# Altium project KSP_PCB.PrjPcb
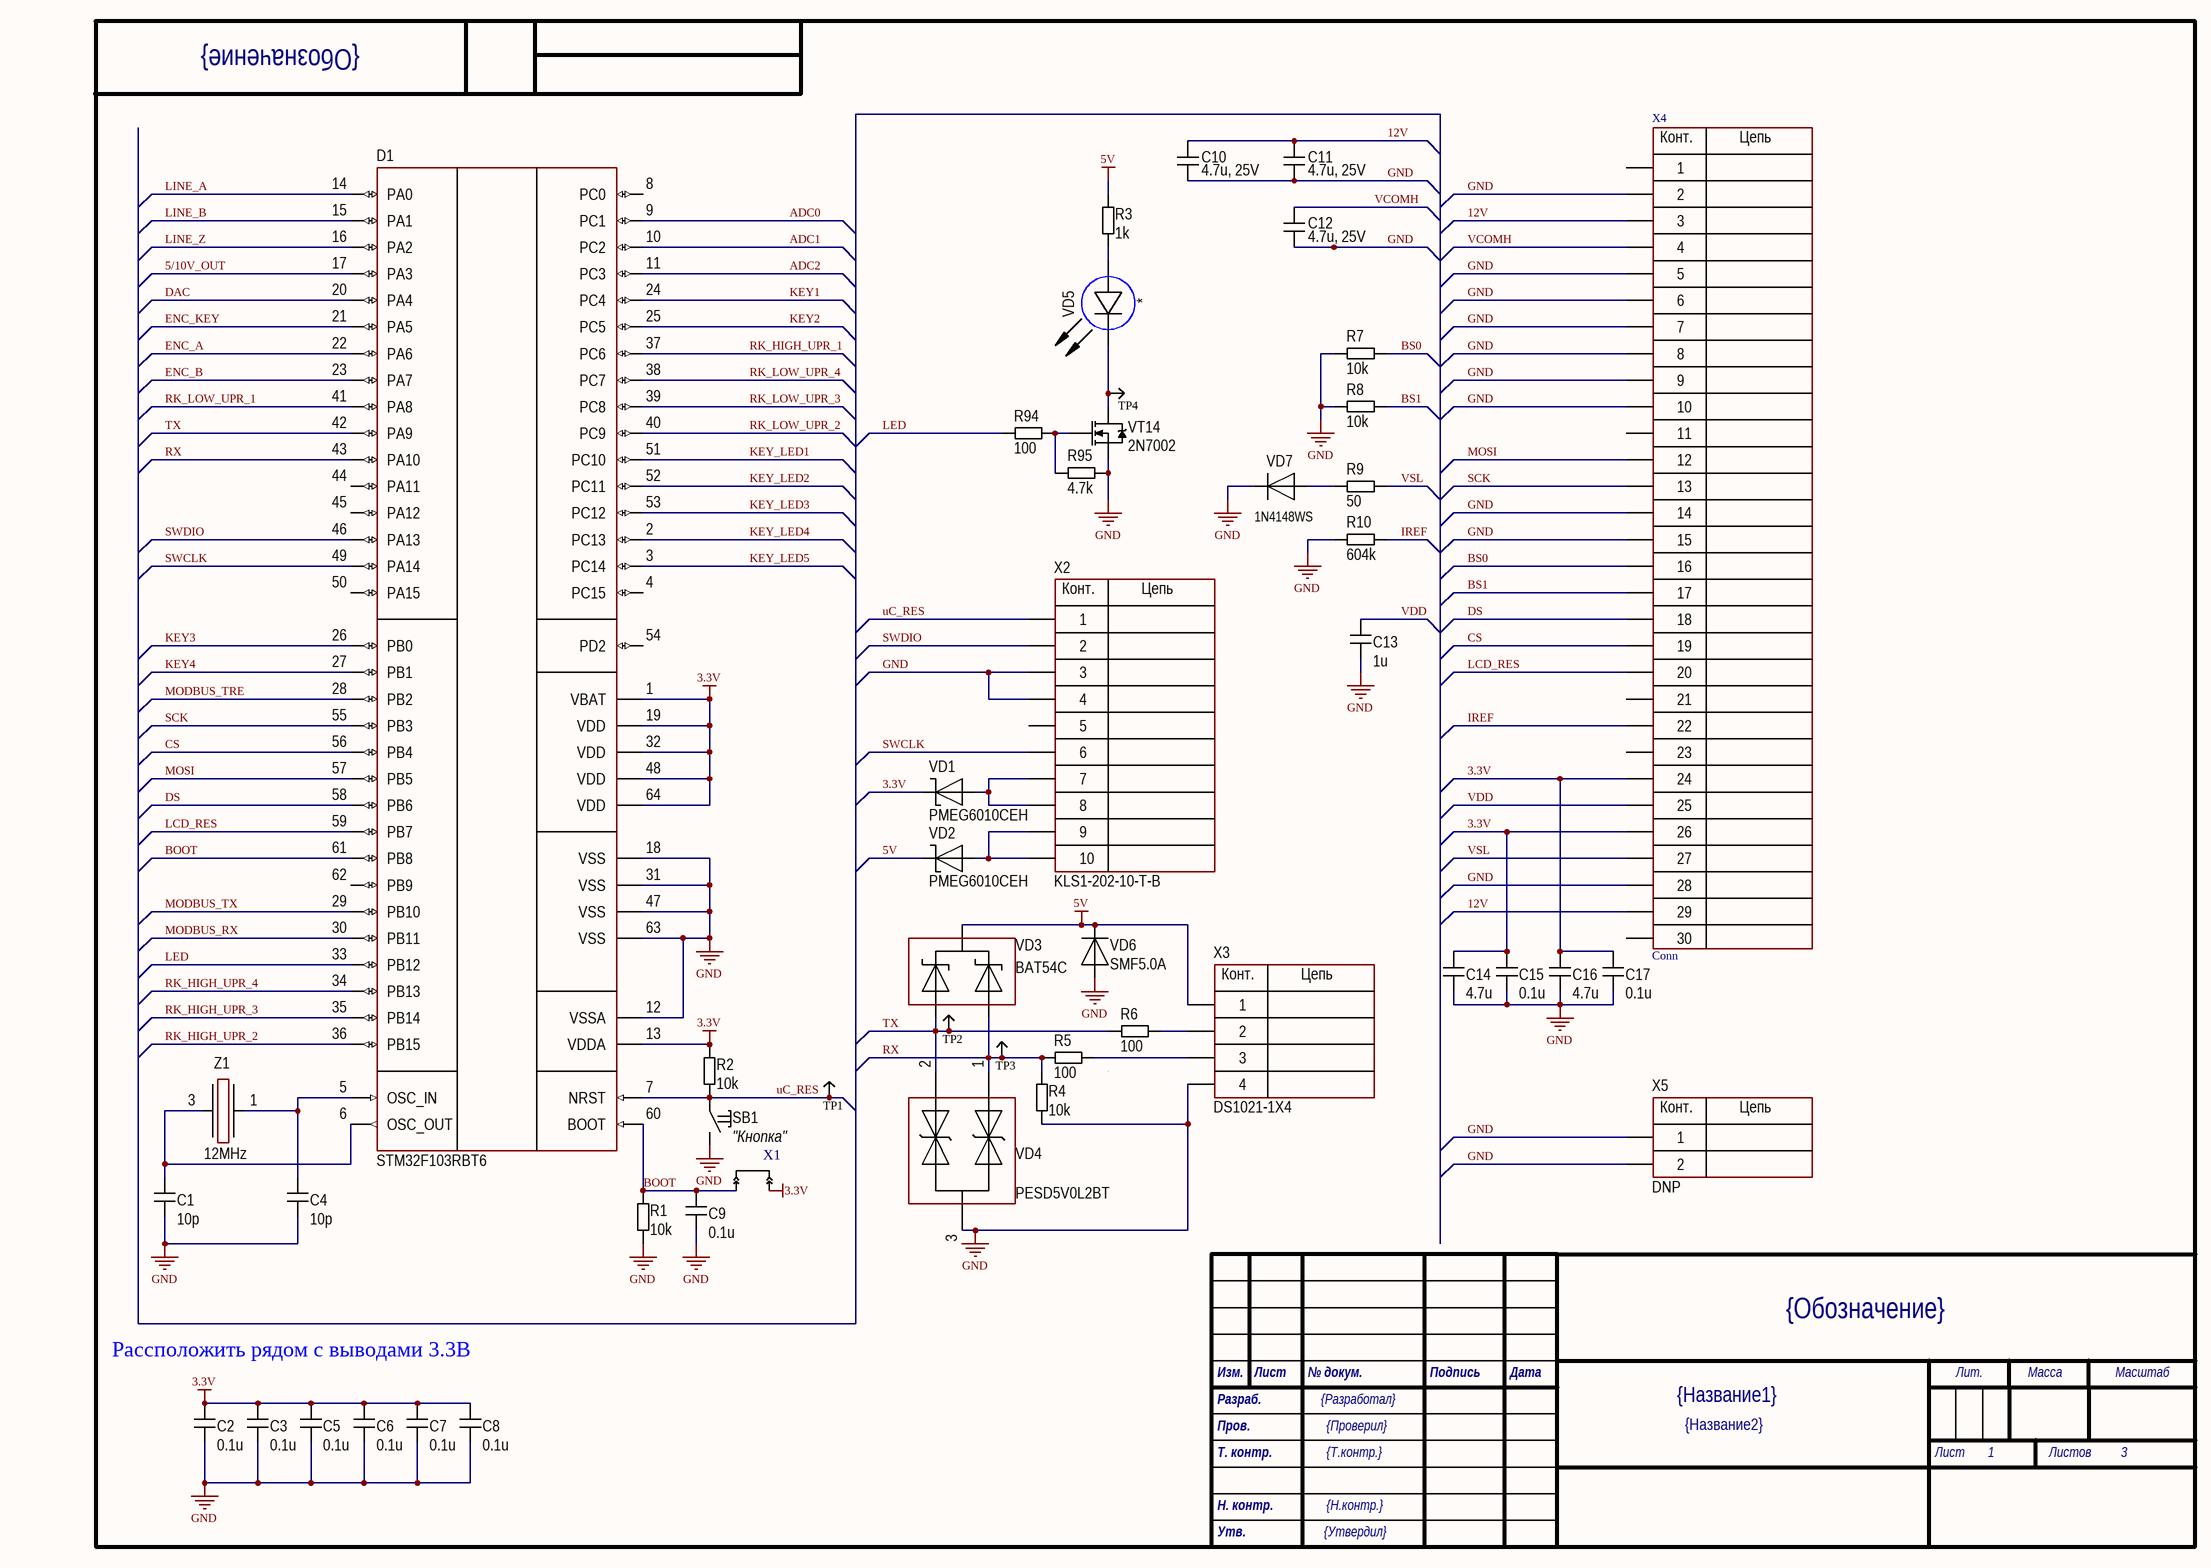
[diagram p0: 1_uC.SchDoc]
3 sheets, 210 parts. Net scope: global (net labels, ports and power ports of the same name join across sheets).
Board file: KSP_PCB.PcbDoc
Sheets:
  1_uC.SchDoc
  2_Connection.SchDoc
  3_RK.SchDoc

## Sheet 1_uC.SchDoc
size 414 x 293 mm; SheetNumber: 1; SheetTotal: 3; PageSetup: Record=PageOptionsZCenterHorizontal=TrueZCenterVertical=TrueZPrintScale=1.00ZXCorrection=0.00ZYCorrection=0.00ZPrintKind=1ZBorderSize=5000000ZLeftOffset=0ZBottomOffset=0ZOrientation=2ZPaperLength=1000ZPaperWidth=1000ZScale=100ZPaperSource=7ZPrintQuality=-4ZMediaType=1ZDitherType=10ZPaperKind=A3ZPrintScaleMode=0; Razrabotal: {Разработал}; Proveril: {Проверил}; Tkontr: {Т.контр.}; Nkontr: {Н.контр.}; Ytverdil: {Утвердил}; Nazvanie1: {Название1}; Nazvanie2: {Название2}; Oboznachenie: {Обозначение}

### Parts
C1  10p  [CH0402C]
C2  0.1u  [CH0603C]
C3  0.1u  [CH0603C]
C4  10p  [CH0402C]
C5  0.1u  [CH0603C]
C6  0.1u  [CH0603C]
C7  0.1u  [CH0603C]
C8  0.1u  [CH0603C]
C9  0.1u  [CH0603C]
C10  4.7u, 25V  [CH0805C]
C11  4.7u, 25V  [CH0805C]
C12  4.7u, 25V  [CH0805C]
C13  1u  [CH0603C]
C14  4.7u  [CH0603C]
C15  0.1u  [CH0603C]
C16  4.7u  [CH0603C]
C17  0.1u  [CH0603C]
D1  STM32F103RBT6  [64-LQFP]
R1  10k  [CH0603R]
R2  10k  [CH0603R]
R3  1k  [CH0805R]
R4  10k  [CH0603R]
R5  100  [CH0603R]
R6  100  [CH0603R]
R7  10k  [CH0603R]
R8  10k  [CH0603R]
R9  50  [CH0603R]
R10  604k  [CH0603R]
R94  100  [CH0603R]
R95  4.7k  [CH0603R]
SB1  "Кнопка"  [TL1014BF160QG]
TP1  (no value)  [TestPoint]
TP2  (no value)  [TestPoint]
TP3  (no value)  [TestPoint]
TP4  (no value)  [TestPoint]
VD1  PMEG6010CEH  [SOD123F]
VD2  PMEG6010CEH  [SOD123F]
VD3  BAT54C  [SOT23_123]
VD4  PESD5V0L2BT  [SOT23_132]
VD5  *  [CH0603LB]
VD6  SMF5.0A  [SOD123F]
VD7  1N4148WS  [SOD323]
VT14  2N7002  [SOT23_123]
X1  JMP-2  [PLS-2]  (value not drawn)
X2  KLS1-202-10-T-B  [CON: IDC-10MS]
X3  DS1021-1X4  [CON: PLS-4]
X4  Conn  [FPC-30]
X5  DNP  [CON: PLS-2]
Z1  12MHz  [OSC: 2520]

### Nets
3.3V: C2.2 C3.2 C5.2 C6.2 C7.2 C8.2 C14.2 C15.2 C16.2 C17.2 D1.1(VBAT) D1.13(VDDA) D1.19(VDD) D1.32(VDD) D1.48(VDD) D1.64(VDD) R2.2 VD1.2 X1.2 X4.24 X4.26
5V: R3.2 VD2.2 VD3.2 VD6.2 X3.1
12V: C10.2 C11.2 X4.3 X4.29
GND: C1.1 C2.1 C3.1 C4.1 C5.1 C6.1 C7.1 C8.1 C9.1 C10.1 C11.1 C12.1 C13.1 C14.1 C15.1 C16.1 C17.1 D1.12(VSSA) D1.18(VSS) D1.31(VSS) D1.47(VSS) D1.63(VSS) R1.1 R4.2 R7.1 R8.1 R10.1 R95.1 SB1.2 VD4.3 VD6.1 VD7.2 VT14.3(S) X2.3 X2.4 X3.4 X4.2 X4.5 X4.6 X4.7 X4.8 X4.9 X4.10 X4.14 X4.15 X4.28 X5.1 X5.2
5/10V_OUT: D1.17(PA3)
ADC0: D1.9(PC1)
ADC1: D1.10(PC2)
ADC2: D1.11(PC3)
BOOT: C9.2 D1.60(BOOT) D1.61(PB8) R1.2 X1.1
BS0: R7.2 X4.16
BS1: R8.2 X4.17
CS: D1.56(PB4) X4.19
DAC: D1.20(PA4)
DS: D1.58(PB6) X4.18
ENC_A: D1.22(PA6)
ENC_B: D1.23(PA7)
ENC_KEY: D1.21(PA5)
IREF: R10.2 X4.22
KEY1: D1.24(PC4)
KEY2: D1.25(PC5)
KEY3: D1.26(PB0)
KEY4: D1.27(PB1)
KEY_LED1: D1.51(PC10)
KEY_LED2: D1.52(PC11)
KEY_LED3: D1.53(PC12)
KEY_LED4: D1.2(PC13)
KEY_LED5: D1.3(PC14)
LCD_RES: D1.59(PB7) X4.20
LED: D1.33(PB12) R94.2
LINE_A: D1.14(PA0)
LINE_B: D1.15(PA1)
LINE_Z: D1.16(PA2)
MODBUS_RX: D1.30(PB11)
MODBUS_TRE: D1.28(PB2)
MODBUS_TX: D1.29(PB10)
MOSI: D1.57(PB5) X4.12
RK_HIGH_UPR_1: D1.37(PC6)
RK_HIGH_UPR_2: D1.36(PB15)
RK_HIGH_UPR_3: D1.35(PB14)
RK_HIGH_UPR_4: D1.34(PB13)
RK_LOW_UPR_1: D1.41(PA8)
RK_LOW_UPR_2: D1.40(PC9)
RK_LOW_UPR_3: D1.39(PC8)
RK_LOW_UPR_4: D1.38(PC7)
RX: D1.43(PA10) R4.1 R5.2 TP3.0 VD3.1 VD4.1
SCK: D1.55(PB3) X4.13
SWCLK: D1.49(PA14) X2.6
SWDIO: D1.46(PA13) X2.2
TX: D1.42(PA9) R6.2 TP2.0 VD3.3 VD4.2
uC_RES: D1.7(NRST) R2.1 SB1.1 TP1.0 X2.1
VCOMH: C12.2 X4.4
VDD: C13.2 X4.25
VSL: R9.2 X4.27
NetC1_2: C1.2 D1.6(OSC_OUT) Z1.3
NetC4_2: C4.2 D1.5(OSC_IN) Z1.1
NetR3_1: R3.1 VD5.1(A)
NetR5_1: R5.1 X3.3
NetR6_1: R6.1 X3.2
NetR9_1: R9.1 VD7.1
NetR94_1: R94.1 R95.2 VT14.1(G)
NetTP4_0: TP4.0 VD5.2(C) VT14.2(D)
NetVD1_1: VD1.1 X2.7 X2.8
NetVD2_1: VD2.1 X2.9 X2.10

Not connected (* = marked no-connect by the designer): D1 4(PC15) 8(PC0) 44(PA11) 45(PA12) 50(PA15) 54(PD2) 62(PB9); X2 5; X4 1 11 21 23 30

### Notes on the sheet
- Рассположить рядом с выводами 3.3В

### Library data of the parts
C1 C4 = Capacitor: Model: AC0402JRNPO9BN100
C2 C3 C5-C9 C15 C17 = Capacitor: Model: 06035C104JAT2A
C10-C12 = Capacitor: Model: 08053C475KAT2A
C13 = Capacitor: Model: 0603B105K250NT
C14 C16 = Capacitor: Model: 06036D475KAT2A
D1 = STM32F103RBT6: Cortex-M3; Manufacturer: STMicroelectronics
R1 R2 R4 R7 R8 = Resistor: Model: CR0603-FX-1002ELF
R3 = Resistor: Model: CR0805-FX-1001ELF
R5 R6 R94 = Resistor: Model: CR0603-JW-101ELF
R9 = Resistor: Model: CR0603-FX-49R9ELF
R10 = Resistor: Model: CR0603-FX-6043ELF
R95 = Resistor: Model: CR0603-FX-4701ELF
SB1 = Tactile switches: 6x6 mm
TP1-TP4 = TestPoint
VD1 VD2 = Diod Schottky
VD3 = Diod Schottky Array v.1
VD4 = TVS Array
VD5 = LED_1: Model: KPT-1608SGC
VD6 = Diod: Part Num: SMAF5.0A
VD7 = Diod
VT14 = N-chanel: Mosfet
X1 = JMP-2: Model: DNP
X2 = 10-Connector
X3 = 4-Connector
X4 = 30-Connector: Model: KLS1-242G-2.0-30-T-R
X5 = 2-Connector
Z1 = Oscillator: Model: ECS-120-10-36B2-JTN-TR

## Sheet 2_Connection.SchDoc
size 414 x 293 mm; SheetNumber: 2; SheetTotal: 3; PageSetup: Record=PageOptionsZCenterHorizontal=TrueZCenterVertical=TrueZPrintScale=1.00ZXCorrection=0.00ZYCorrection=0.00ZPrintKind=1ZBorderSize=5000000ZLeftOffset=0ZBottomOffset=0ZOrientation=2ZPaperLength=1000ZPaperWidth=1000ZScale=100ZPaperSource=7ZPrintQuality=-4ZMediaType=1ZDitherType=10ZPaperKind=A3ZPrintScaleMode=0; Razrabotal: {Разработал}; Proveril: {Проверил}; Tkontr: {Т.контр.}; Nkontr: {Н.контр.}; Ytverdil: {Утвердил}; Nazvanie1: {Название1}; Nazvanie2: {Название2}; Oboznachenie: {Обозначение}
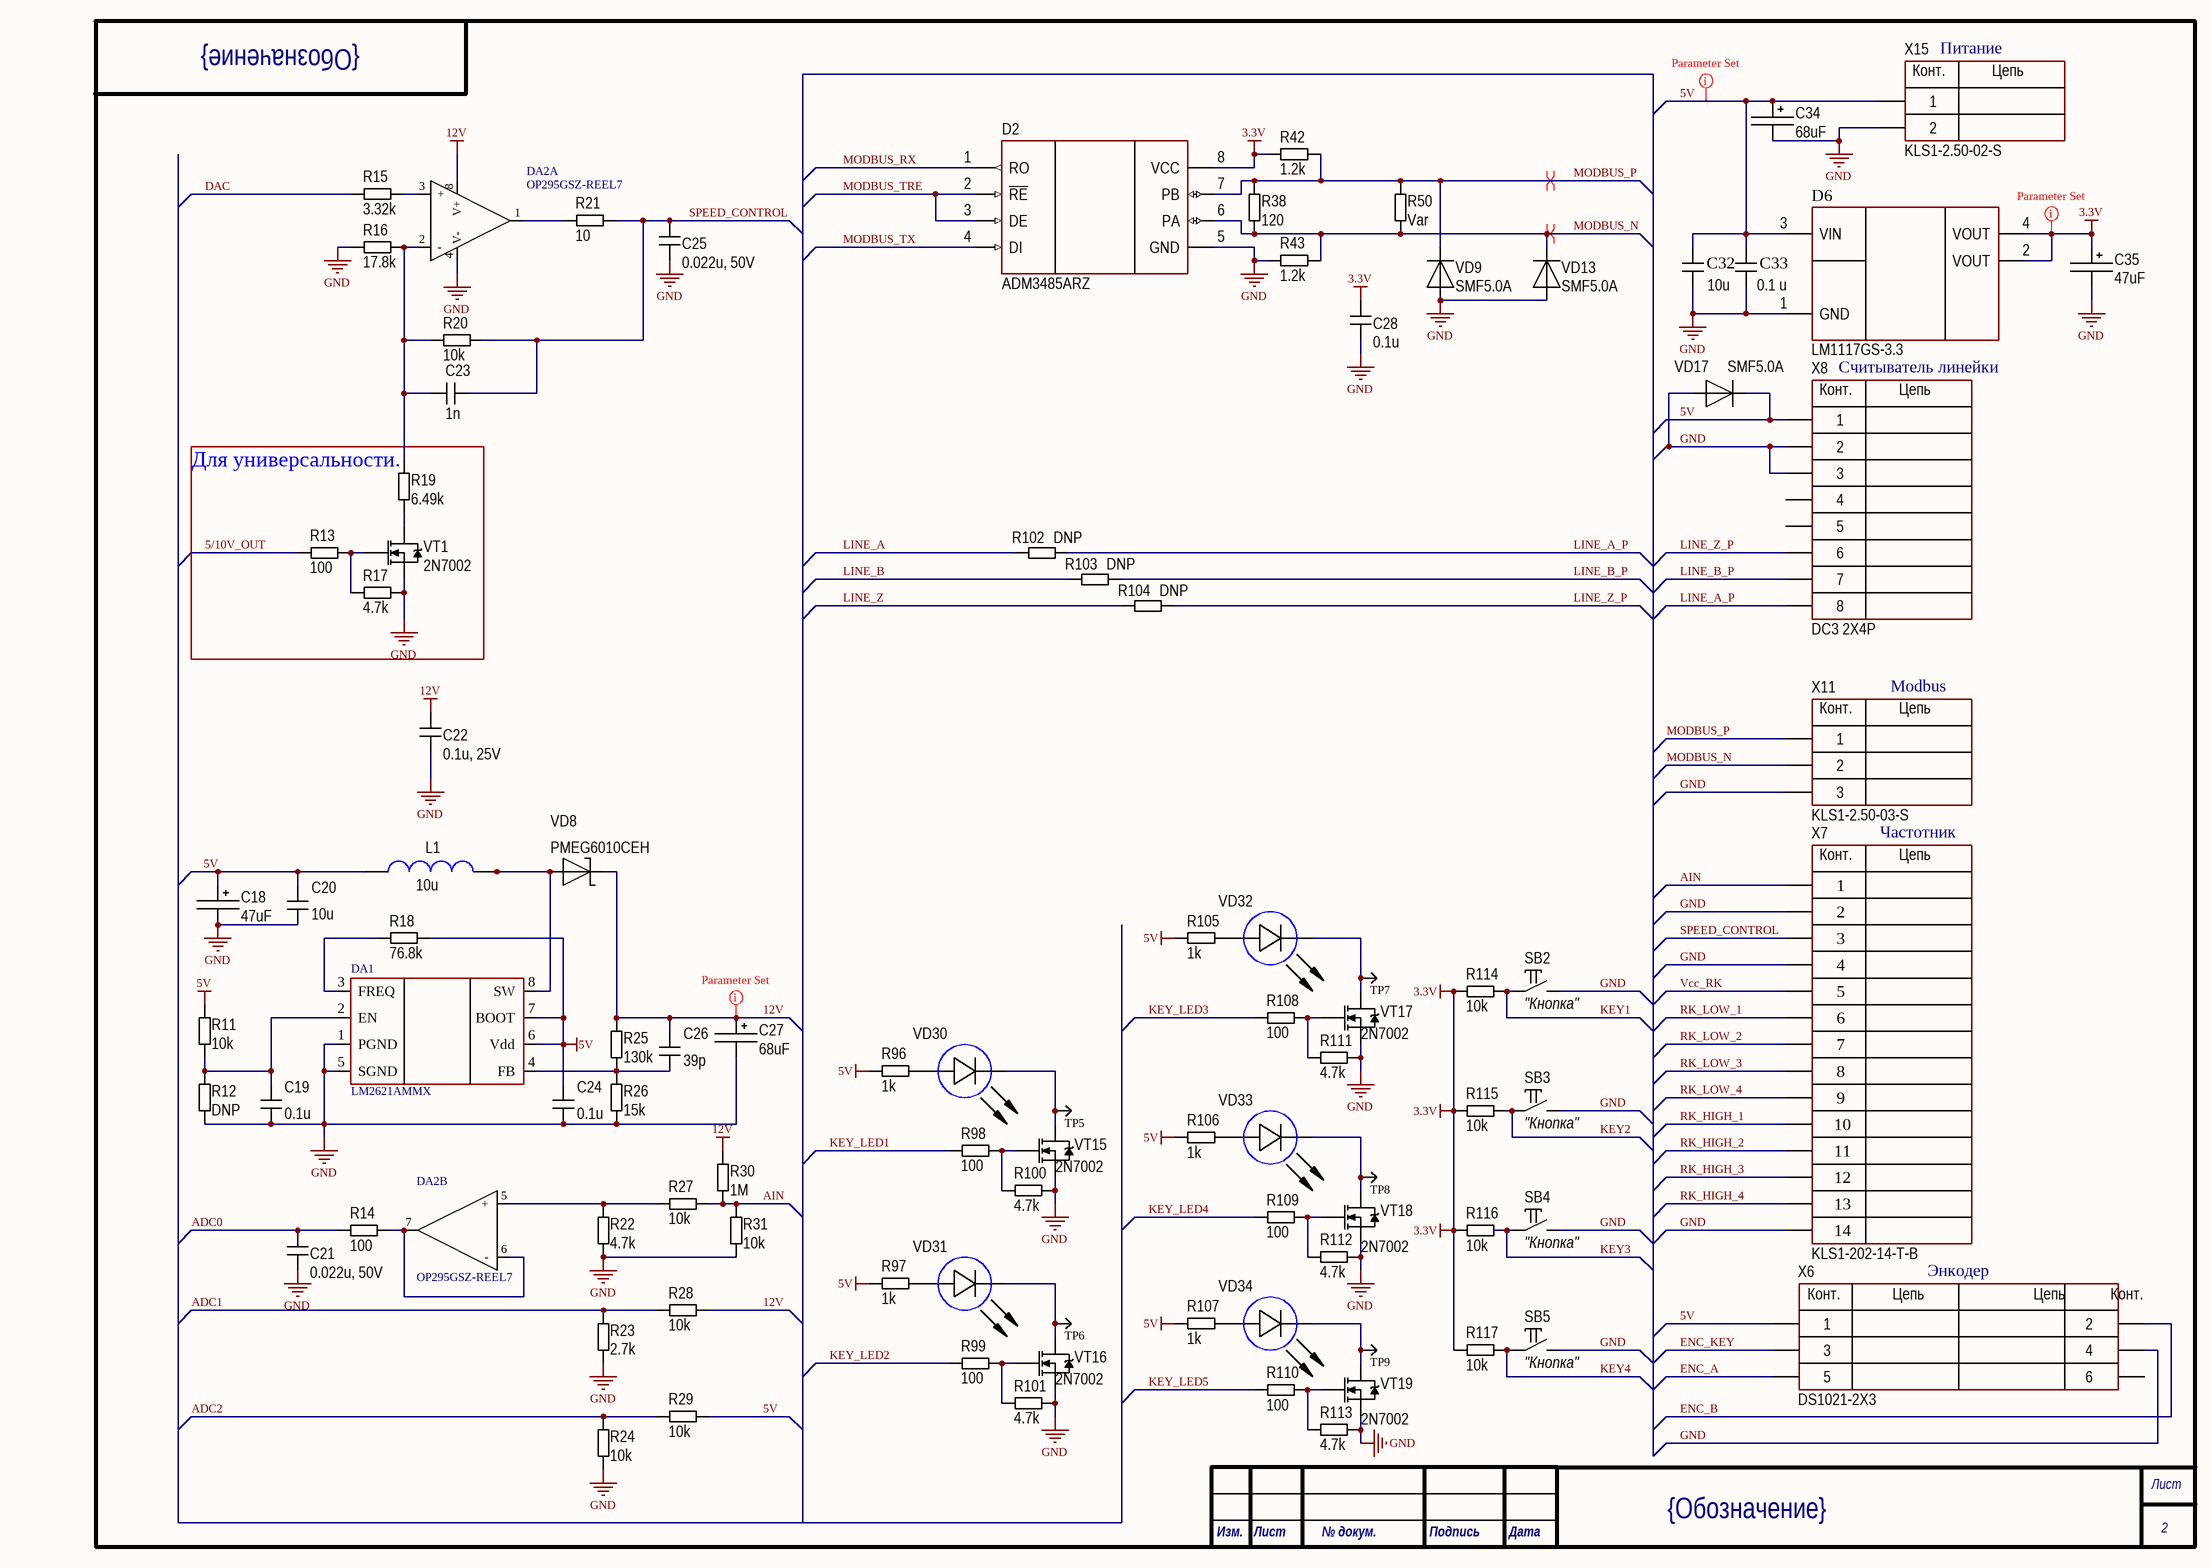
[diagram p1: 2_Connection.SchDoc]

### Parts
C18  47uF  [TANTAL_B]
C19  0.1u  [CH0603C]
C20  10u  [CH0603C]
C21  0.022u, 50V  [CH0603C]
C22  0.1u, 25V  [CH0603C]
C23  1n  [CH0603C]
C24  0.1u  [CH0603C]
C25  0.022u, 50V  [CH0603C]
C26  39p  [CH0603C]
C27  68uF  [TANTAL_D]
C28  0.1u  [CH0603C]
C32  10u  [CH0805C]
C33  0.1 u  [CH0603C]
C34  68uF  [TANTAL_B]
C35  47uF  [TANTAL_A]
D2  ADM3485ARZ  [8-SOIC]
D6  LM1117GS-3.3  [SOT223]
DA1  LM2621AMMX  [8-SSOP]
DA2  OP295GSZ-REEL7  [8-SOIC]  (parts A,B of 2)
L1  10u  [IND: IHLP2020]
R11  10k  [CH0603R]
R12  DNP  [CH0603R]
R13  100  [CH0603R]
R14  100  [CH0603R]
R15  3.32k  [CH0603R]
R16  17.8k  [CH0603R]
R17  4.7k  [CH0603R]
R18  76.8k  [CH0603R]
R19  6.49k  [CH0603R]
R20  10k  [CH0603R]
R21  10  [CH0603R]
R22  4.7k  [CH0603R]
R23  2.7k  [CH0603R]
R24  10k  [CH0603R]
R25  130k  [CH0603R]
R26  15k  [CH0603R]
R27  10k  [CH0603R]
R28  10k  [CH0603R]
R29  10k  [CH0603R]
R30  1M  [CH0603R]
R31  10k  [CH0603R]
R38  120  [CH1206R]
R42  1.2k  [CH0603R]
R43  1.2k  [CH0603R]
R50  Var  [CH1206R]
R96  1k  [CH0805R]
R97  1k  [CH0805R]
R98  100  [CH0603R]
R99  100  [CH0603R]
R100  4.7k  [CH0603R]
R101  4.7k  [CH0603R]
R102  DNP  [CH0603R]
R103  DNP  [CH0603R]
R104  DNP  [CH0603R]
R105  1k  [CH0805R]
R106  1k  [CH0805R]
R107  1k  [CH0805R]
R108  100  [CH0603R]
R109  100  [CH0603R]
R110  100  [CH0603R]
R111  4.7k  [CH0603R]
R112  4.7k  [CH0603R]
R113  4.7k  [CH0603R]
R114  10k  [CH0603R]
R115  10k  [CH0603R]
R116  10k  [CH0603R]
R117  10k  [CH0603R]
SB2  "Кнопка"  [BUT: SKQGADE010]
SB3  "Кнопка"  [BUT: SKQGADE010]
SB4  "Кнопка"  [BUT: SKQGADE010]
SB5  "Кнопка"  [BUT: SKQGADE010]
TP5  (no value)  [TestPoint]
TP6  (no value)  [TestPoint]
TP7  (no value)  [TestPoint]
TP8  (no value)  [TestPoint]
TP9  (no value)  [TestPoint]
VD8  PMEG6010CEH  [SOD123F]
VD9  SMF5.0A  [SOD123F]
VD13  SMF5.0A  [SOD123F]
VD17  SMF5.0A  [SOD123F]
VD30  BLUE  [CH0603LB]  (value not drawn)
VD31  BLUE  [CH0603LB]  (value not drawn)
VD32  BLUE  [CH0603LB]  (value not drawn)
VD33  BLUE  [CH0603LB]  (value not drawn)
VD34  BLUE  [CH0603LB]  (value not drawn)
VT1  2N7002  [SOT23_123]
VT15  2N7002  [SOT23_123]
VT16  2N7002  [SOT23_123]
VT17  2N7002  [SOT23_123]
VT18  2N7002  [SOT23_123]
VT19  2N7002  [SOT23_123]
X6  DS1021-2X3  [CON: PLD-6 (without body)]
X7  KLS1-202-14-T-B  [CON: IDC-14MS]
X8  DC3 2X4P  [CON: DC3 2x4P]
X11  KLS1-2.50-03-S  [CON: CWF-3]
X15  KLS1-2.50-02-S  [CON: CWF-2]

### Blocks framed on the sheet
Для универсальности.: R13 R17 R19 VT1

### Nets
3.3V: C28.2 C35.1 D2.8(VCC) D6.2(VOUT) D6.4(VOUT) R42.2 R114.2 R115.2 R116.2 R117.2
5V: C18.1 C20.2 C24.2 C32.2 C33.2 C34.1 D6.3(VIN) DA1.6(Vdd) DA1.7(BOOT) L1.2 R11.1 R18.1 R29.1 R96.2 R97.2 R105.2 R106.2 R107.2 VD17.2 X6.1 X8.1 X15.1
12V: C22.2 C26.2 C27.1 DA2.8(V+) R25.1 R28.1 R30.1 VD8.2
GND: C18.2 C19.1 C20.1 C21.1 C22.1 C24.1 C25.1 C27.2 C28.1 C32.1 C33.1 C34.2 C35.2 D2.5(GND) D6.1(GND) DA1.1(PGND) DA1.5(SGND) DA2.4(V-) R12.2 R16.2 R17.1 R22.2 R23.2 R24.2 R26.2 R31.2 R43.2 R100.1 R101.1 R111.1 R112.1 R113.1 SB2.2 SB3.2 SB4.2 SB5.2 VD9.1 VD13.1 VD17.1 VT1.3(S) VT15.3(S) VT16.3(S) VT17.3(S) VT18.3(S) VT19.3(S) X6.4 X7.2 X7.4 X7.14 X8.2 X8.3 X11.3 X15.2
5/10V_OUT: R13.2
ADC0: C21.2 R14.1
ADC1: R23.1 R28.2
ADC2: R24.1 R29.2
AIN: R27.1 R30.2 R31.1 X7.1
DAC: R15.2
ENC_A: X6.5
ENC_B: X6.2
ENC_KEY: X6.3
KEY1: R114.1 SB2.1
KEY2: R115.1 SB3.1
KEY3: R116.1 SB4.1
KEY4: R117.1 SB5.1
KEY_LED1: R98.2
KEY_LED2: R99.2
KEY_LED3: R108.2
KEY_LED4: R109.2
KEY_LED5: R110.2
LINE_A: R102.2
LINE_A_P: R102.1 X8.8
LINE_B: R103.2
LINE_B_P: R103.1 X8.7
LINE_Z: R104.2
LINE_Z_P: R104.1 X8.6
MODBUS_N: D2.6(PA) R38.1 R43.1 R50.1 VD13.2 X11.2
MODBUS_P: D2.7(PB) R38.2 R42.1 R50.2 VD9.2 X11.1
MODBUS_RX: D2.1(RO)
MODBUS_TRE: D2.2(~{RE}) D2.3(DE)
MODBUS_TX: D2.4(DI)
RK_HIGH_1: X7.10
RK_HIGH_2: X7.11
RK_HIGH_3: X7.12
RK_HIGH_4: X7.13
RK_LOW_1: X7.6
RK_LOW_2: X7.7
RK_LOW_3: X7.8
RK_LOW_4: X7.9
SPEED_CONTROL: C23.1 C25.2 R20.1 R21.1 X7.3
Vcc_RK: X7.5
NetC19_2: C19.2 DA1.2(EN) R11.2 R12.1
NetC23_2: C23.2 DA2.2(-) R16.1 R19.1 R20.2
NetC26_1: C26.1 DA1.4(FB) R25.2 R26.1
NetDA1_3: DA1.3(FREQ) R18.2
NetDA1_8: DA1.8(SW) L1.1 VD8.1
NetDA2_1: DA2.1(OUT) R21.2
NetDA2_3: DA2.3(+) R15.1
NetDA2_5: DA2.5(+) R22.1 R27.2
NetDA2_6: DA2.6(-) DA2.7(OUT) R14.2
NetR13_1: R13.1 R17.2 VT1.1(G)
NetR19_2: R19.2 VT1.2(D)
NetR96_1: R96.1 VD30.1(A)
NetR97_1: R97.1 VD31.1(A)
NetR98_1: R98.1 R100.2 VT15.1(G)
NetR99_1: R99.1 R101.2 VT16.1(G)
NetR105_1: R105.1 VD32.1(A)
NetR106_1: R106.1 VD33.1(A)
NetR107_1: R107.1 VD34.1(A)
NetR108_1: R108.1 R111.2 VT17.1(G)
NetR109_1: R109.1 R112.2 VT18.1(G)
NetR110_1: R110.1 R113.2 VT19.1(G)
NetTP5_0: TP5.0 VD30.2(C) VT15.2(D)
NetTP6_0: TP6.0 VD31.2(C) VT16.2(D)
NetTP7_0: TP7.0 VD32.2(C) VT17.2(D)
NetTP8_0: TP8.0 VD33.2(C) VT18.2(D)
NetTP9_0: TP9.0 VD34.2(C) VT19.2(D)

Not connected (* = marked no-connect by the designer): X6 6; X8 4 5

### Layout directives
differential pair: MODBUS_N, MODBUS_P
rule Supply Nets [Voltage = 5.000]: 5V
rule Supply Nets [Voltage = 12.00]: 12V
rule Supply Nets [Voltage = 3.300]: 3.3V

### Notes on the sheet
- Питание
- Считыватель линейки
- Modbus
- Частотник
- (near X6) Энкодер

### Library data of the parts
C18 = TantalCap: Model: 293D476X9010B2TE3
C19 C22 C24 C28 C33 = Capacitor: Model: 06035C104JAT2A
C20 C32 = Capacitor: Model: GRM21BR71A106KE51
C21 C25 = Capacitor: Model: 06035C223JAT2A
C23 = Capacitor: Model: 06035A102JAT2A
C26 = Capacitor: Model: CC0603JRNPO9BN390
C27 = TantalCap: Model: 293D686X9020D2TE3
C34 = TantalCap: Model: 293D686X9010B2TE3
C35 = TantalCap: Model: 293D476X96R3A2TE3
D2 = ADM3485ARZ: RS485; Manufacturer: Analog Devices Inc.; Model: ADM3485ARZ-REEL7
D6 = LDL1117S33R: LDO; Manufacturer: STMicroelectronics
DA1 = LM2623AMMX
DA2 = OP295
L1 = Inductor: Model: IHLP2020CZER100M11
R11 R20 R24 R27-R29 R31 R114-R117 = Resistor: Model: CR0603-FX-1002ELF
R12 R102-R104 = Resistor
R13 R14 R98 R99 R108-R110 = Resistor: Model: CR0603-JW-101ELF
R15 = Resistor: Model: CR0603-FX-3321ELF
R16 = Resistor: Model: CR0603-FX-1782ELF
R17 R22 R100 R101 R111-R113 = Resistor: Model: CR0603-FX-4701ELF
R18 = Resistor: Model: CR0603-FX-7682ELF
R19 = Resistor: Model: CR0603-FX-6491ELF
R21 = Resistor: Model: CR0603-FX-10R0ELF
R23 = Resistor: Model: CR0603-FX-2701ELF
R25 = Resistor: Model: CR0603-FX-1303ELF
R26 = Resistor: Model: CR0603-FX-1502ELF
R30 = Resistor: Model: CR0603-FX-1004ELF
R38 = Resistor: Model: CR1206-FX-1200ELF
R42 R43 = Resistor: Model: CR0603-FX-1201ELF
R50 = Resistor: Model: JMV0805S5R6T661
R96 R97 R105-R107 = Resistor: Model: CR0805-FX-1001ELF
SB2-SB5 = Tactile switches: 6x6 mm; Model: SKQGADE010
TP5-TP9 = TestPoint
VD8 = Diod Schottky
VD9 VD13 VD17 = Diod: Part Num: SMAF5.0A
VD30-VD34 = LED_1: Model: KPT-1608SGC
VT1 VT15-VT19 = N-chanel: Mosfet
X6 = 6(2)-Connector
X7 = 14-Connector
X8 = 8-Connector
X11 = 3-Connector
X15 = 2-Connector

## Sheet 3_RK.SchDoc
size 414 x 293 mm; SheetNumber: 3; SheetTotal: 3
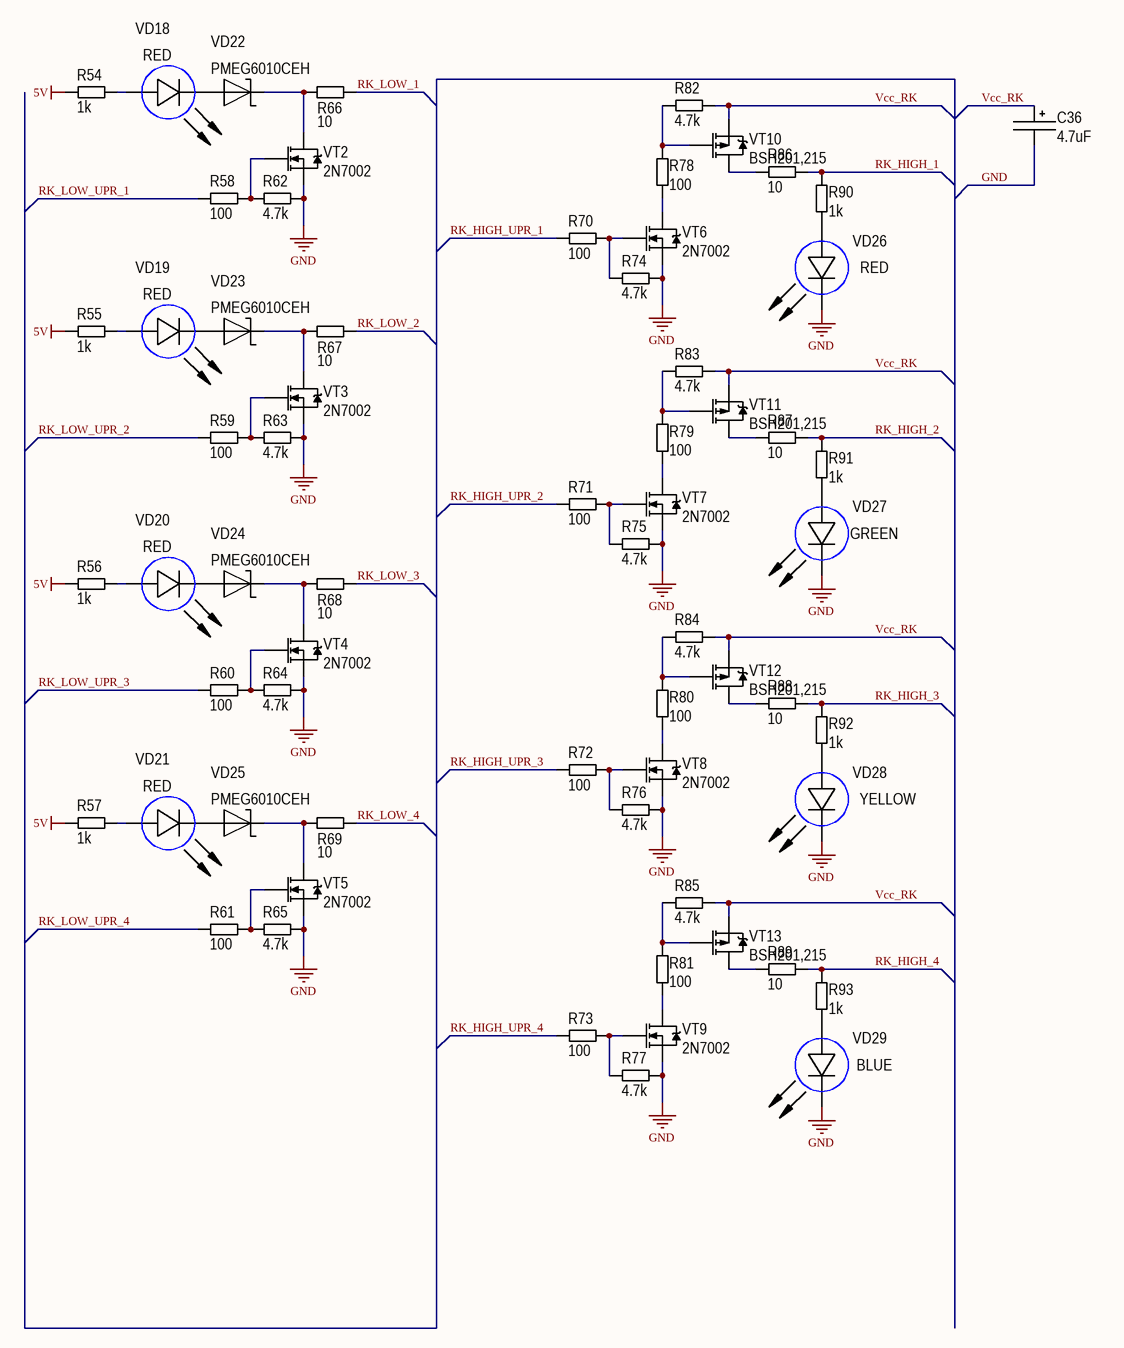
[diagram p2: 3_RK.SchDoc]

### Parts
C36  4.7uF  [TANTAL_C]
R54  1k  [CH0805R]
R55  1k  [CH0805R]
R56  1k  [CH0805R]
R57  1k  [CH0805R]
R58  100  [CH0603R]
R59  100  [CH0603R]
R60  100  [CH0603R]
R61  100  [CH0603R]
R62  4.7k  [CH0603R]
R63  4.7k  [CH0603R]
R64  4.7k  [CH0603R]
R65  4.7k  [CH0603R]
R66  10  [CH0603R]
R67  10  [CH0603R]
R68  10  [CH0603R]
R69  10  [CH0603R]
R70  100  [CH0603R]
R71  100  [CH0603R]
R72  100  [CH0603R]
R73  100  [CH0603R]
R74  4.7k  [CH0603R]
R75  4.7k  [CH0603R]
R76  4.7k  [CH0603R]
R77  4.7k  [CH0603R]
R78  100  [CH0603R]
R79  100  [CH0603R]
R80  100  [CH0603R]
R81  100  [CH0603R]
R82  4.7k  [CH0603R]
R83  4.7k  [CH0603R]
R84  4.7k  [CH0603R]
R85  4.7k  [CH0603R]
R86  10  [CH0603R]
R87  10  [CH0603R]
R88  10  [CH0603R]
R89  10  [CH0603R]
R90  1k  [CH0805R]
R91  1k  [CH0805R]
R92  1k  [CH0805R]
R93  1k  [CH0805R]
VD18  RED  [CH0603LB]
VD19  RED  [CH0603LB]
VD20  RED  [CH0603LB]
VD21  RED  [CH0603LB]
VD22  PMEG6010CEH  [SOD123F]
VD23  PMEG6010CEH  [SOD123F]
VD24  PMEG6010CEH  [SOD123F]
VD25  PMEG6010CEH  [SOD123F]
VD26  RED  [CH0603LB]
VD27  GREEN  [CH0603LB]
VD28  YELLOW  [CH0603LB]
VD29  BLUE  [CH0603LB]
VT2  2N7002  [SOT23_123]
VT3  2N7002  [SOT23_123]
VT4  2N7002  [SOT23_123]
VT5  2N7002  [SOT23_123]
VT6  2N7002  [SOT23_123]
VT7  2N7002  [SOT23_123]
VT8  2N7002  [SOT23_123]
VT9  2N7002  [SOT23_123]
VT10  BSH201,215  [SOT23_123]
VT11  BSH201,215  [SOT23_123]
VT12  BSH201,215  [SOT23_123]
VT13  BSH201,215  [SOT23_123]

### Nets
5V: R54.2 R55.2 R56.2 R57.2
GND: C36.2 R62.1 R63.1 R64.1 R65.1 R74.1 R75.1 R76.1 R77.1 VD26.2(C) VD27.2(C) VD28.2(C) VD29.2(C) VT2.3(S) VT3.3(S) VT4.3(S) VT5.3(S) VT6.3(S) VT7.3(S) VT8.3(S) VT9.3(S)
RK_HIGH_1: R86.1 R90.2
RK_HIGH_2: R87.1 R91.2
RK_HIGH_3: R88.1 R92.2
RK_HIGH_4: R89.1 R93.2
RK_HIGH_UPR_1: R70.2
RK_HIGH_UPR_2: R71.2
RK_HIGH_UPR_3: R72.2
RK_HIGH_UPR_4: R73.2
RK_LOW_1: R66.1
RK_LOW_2: R67.1
RK_LOW_3: R68.1
RK_LOW_4: R69.1
RK_LOW_UPR_1: R58.2
RK_LOW_UPR_2: R59.2
RK_LOW_UPR_3: R60.2
RK_LOW_UPR_4: R61.2
Vcc_RK: C36.1 R82.1 R83.1 R84.1 R85.1 VT10.3(S) VT11.3(S) VT12.3(S) VT13.3(S)
NetR54_1: R54.1 VD18.1(A)
NetR55_1: R55.1 VD19.1(A)
NetR56_1: R56.1 VD20.1(A)
NetR57_1: R57.1 VD21.1(A)
NetR58_1: R58.1 R62.2 VT2.1(G)
NetR59_1: R59.1 R63.2 VT3.1(G)
NetR60_1: R60.1 R64.2 VT4.1(G)
NetR61_1: R61.1 R65.2 VT5.1(G)
NetR66_2: R66.2 VD22.2 VT2.2(D)
NetR67_2: R67.2 VD23.2 VT3.2(D)
NetR68_2: R68.2 VD24.2 VT4.2(D)
NetR69_2: R69.2 VD25.2 VT5.2(D)
NetR70_1: R70.1 R74.2 VT6.1(G)
NetR71_1: R71.1 R75.2 VT7.1(G)
NetR72_1: R72.1 R76.2 VT8.1(G)
NetR73_1: R73.1 R77.2 VT9.1(G)
NetR78_1: R78.1 R82.2 VT10.1(G)
NetR78_2: R78.2 VT6.2(D)
NetR79_1: R79.1 R83.2 VT11.1(G)
NetR79_2: R79.2 VT7.2(D)
NetR80_1: R80.1 R84.2 VT12.1(G)
NetR80_2: R80.2 VT8.2(D)
NetR81_1: R81.1 R85.2 VT13.1(G)
NetR81_2: R81.2 VT9.2(D)
NetR86_2: R86.2 VT10.2(D)
NetR87_2: R87.2 VT11.2(D)
NetR88_2: R88.2 VT12.2(D)
NetR89_2: R89.2 VT13.2(D)
NetR90_1: R90.1 VD26.1(A)
NetR91_1: R91.1 VD27.1(A)
NetR92_1: R92.1 VD28.1(A)
NetR93_1: R93.1 VD29.1(A)
NetVD18_2: VD18.2(C) VD22.1
NetVD19_2: VD19.2(C) VD23.1
NetVD20_2: VD20.2(C) VD24.1
NetVD21_2: VD21.2(C) VD25.1

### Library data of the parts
C36 = TantalCap: Model: 293D475X9035C2TE3
R54-R57 R90-R93 = Resistor: Model: CR0805-FX-1001ELF
R58-R61 R70-R73 R78-R81 = Resistor: Model: CR0603-JW-101ELF
R62-R65 R74-R77 R82-R85 = Resistor: Model: CR0603-FX-4701ELF
R66-R69 R86-R89 = Resistor
VD18-VD21 VD26-VD29 = LED_1: Model: KPT-1608SGC
VD22-VD25 = Diod Schottky
VT2-VT9 = N-chanel: Mosfet
VT10-VT13 = P-chanel: Mosfet

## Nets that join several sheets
3.3V: 1_uC (21 pins), 2_Connection (10 pins)
5V: 1_uC (5 pins), 2_Connection (22 pins), 3_RK (R54.2 R55.2 R56.2 R57.2)
12V: 1_uC (C10.2 C11.2 X4.3 X4.29), 2_Connection (8 pins)
GND: 1_uC (48 pins), 2_Connection (53 pins), 3_RK (21 pins)
5/10V_OUT: 1_uC (D1.17), 2_Connection (R13.2)
ADC0: 1_uC (D1.9), 2_Connection (C21.2 R14.1)
ADC1: 1_uC (D1.10), 2_Connection (R23.1 R28.2)
ADC2: 1_uC (D1.11), 2_Connection (R24.1 R29.2)
DAC: 1_uC (D1.20), 2_Connection (R15.2)
ENC_A: 1_uC (D1.22), 2_Connection (X6.5)
ENC_B: 1_uC (D1.23), 2_Connection (X6.2)
ENC_KEY: 1_uC (D1.21), 2_Connection (X6.3)
KEY1: 1_uC (D1.24), 2_Connection (R114.1 SB2.1)
KEY2: 1_uC (D1.25), 2_Connection (R115.1 SB3.1)
KEY3: 1_uC (D1.26), 2_Connection (R116.1 SB4.1)
KEY4: 1_uC (D1.27), 2_Connection (R117.1 SB5.1)
KEY_LED1: 1_uC (D1.51), 2_Connection (R98.2)
KEY_LED2: 1_uC (D1.52), 2_Connection (R99.2)
KEY_LED3: 1_uC (D1.53), 2_Connection (R108.2)
KEY_LED4: 1_uC (D1.2), 2_Connection (R109.2)
KEY_LED5: 1_uC (D1.3), 2_Connection (R110.2)
LINE_A: 1_uC (D1.14), 2_Connection (R102.2)
LINE_B: 1_uC (D1.15), 2_Connection (R103.2)
LINE_Z: 1_uC (D1.16), 2_Connection (R104.2)
MODBUS_RX: 1_uC (D1.30), 2_Connection (D2.1)
MODBUS_TRE: 1_uC (D1.28), 2_Connection (D2.2 D2.3)
MODBUS_TX: 1_uC (D1.29), 2_Connection (D2.4)
RK_HIGH_1: 2_Connection (X7.10), 3_RK (R86.1 R90.2)
RK_HIGH_2: 2_Connection (X7.11), 3_RK (R87.1 R91.2)
RK_HIGH_3: 2_Connection (X7.12), 3_RK (R88.1 R92.2)
RK_HIGH_4: 2_Connection (X7.13), 3_RK (R89.1 R93.2)
RK_HIGH_UPR_1: 1_uC (D1.37), 3_RK (R70.2)
RK_HIGH_UPR_2: 1_uC (D1.36), 3_RK (R71.2)
RK_HIGH_UPR_3: 1_uC (D1.35), 3_RK (R72.2)
RK_HIGH_UPR_4: 1_uC (D1.34), 3_RK (R73.2)
RK_LOW_1: 2_Connection (X7.6), 3_RK (R66.1)
RK_LOW_2: 2_Connection (X7.7), 3_RK (R67.1)
RK_LOW_3: 2_Connection (X7.8), 3_RK (R68.1)
RK_LOW_4: 2_Connection (X7.9), 3_RK (R69.1)
RK_LOW_UPR_1: 1_uC (D1.41), 3_RK (R58.2)
RK_LOW_UPR_2: 1_uC (D1.40), 3_RK (R59.2)
RK_LOW_UPR_3: 1_uC (D1.39), 3_RK (R60.2)
RK_LOW_UPR_4: 1_uC (D1.38), 3_RK (R61.2)
Vcc_RK: 2_Connection (X7.5), 3_RK (9 pins)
